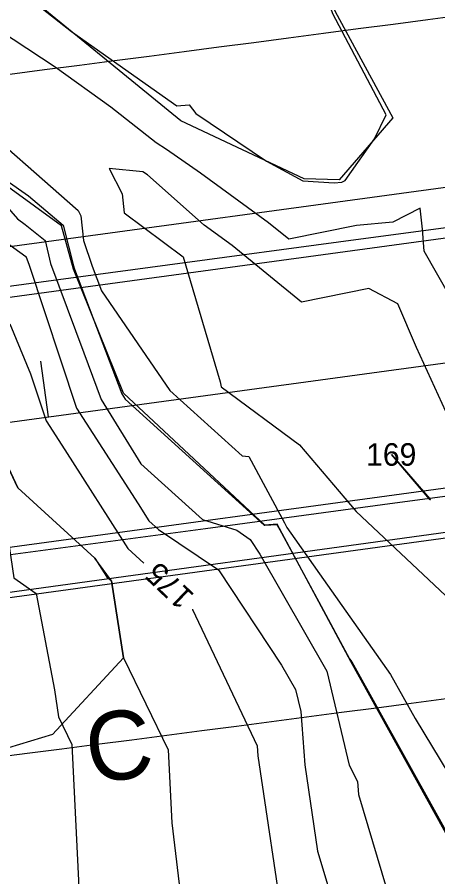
# Model space of a CAD drawing. Extents: x 2086416 to 2115205, y 575507 to 632762.
# Drawn here: x 2111519.4 to 2111556.7, y 581610 to 581686.3 of the extents above; entities that cross this region are included whole.
import ezdxf

# ---------------------------------------------------------------- set-up
doc = ezdxf.new("R2010")
doc.units = 0
for name, color, linetype in [('Default', 7, 'Continuous'), ('DTM Contours Major', 7, 'Continuous'), ('DTM Contours Major Text', 7, 'Continuous'), ('DTM Contours Minor', 7, 'Continuous'), ('DTM Contours Minor Text', 7, 'Continuous'), ('Exist Hydro Stream or Body of Water', 7, 'Continuous'), ('Exist Right of Way Line', 7, 'Continuous'), ('Exist Structure Major Deck Tunnel Box Culvert', 7, 'Continuous'), ('Prop Horizontal Alignment', 7, 'Continuous'), ('Prop Horizontal Alignment Tick Small', 7, 'Continuous'), ('Prop Roadway Bridge', 7, 'Continuous'), ('Prop SS Cut Line', 7, 'Continuous'), ('Prop SS Cut Text', 7, 'Continuous')]:
    doc.layers.add(name, color=color, linetype=linetype)

msp = doc.modelspace()

# ---------------------------------------------------------------- linework, layer by layer
at = {"layer": 'Default'}
for p, q in [((2111430.061, 581649.328), (2112312.029, 581769.688)), ((2111433.036, 581627.53), (2112315.004, 581747.89)), ((2111508.232, 581633.802), (2112048.04, 581707.887))]:
    msp.add_line(p, q, dxfattribs=at)
at = {"layer": 'DTM Contours Major'}
for points in [[(2111563.624, 581644.535), (2111557.765, 581650.557), (2111554.83, 581656.943), (2111553.167, 581660.831), (2111550.584, 581662.207), (2111544.629, 581660.993), (2111538.463, 581666.005), (2111535.965, 581667.83), (2111530.949, 581672.288), (2111530.521, 581672.558), (2111527.53, 581672.834), (2111528.703, 581670.603), (2111528.883, 581668.916), (2111534.119, 581665.006), (2111537.381, 581653.906), (2111537.496, 581653.447), (2111544.432, 581648.303), (2111549.461, 581642.401), (2111557.401, 581634.942)], [(2111518.722, 581659.055), (2111520.566, 581654.612), (2111521.942, 581650.454), (2111523.608, 581647.867), (2111529.184, 581639.091), (2111530.614, 581637.815)], [(2111534.94, 581633.703), (2111534.951, 581633.685), (2111540.685, 581621.595), (2111540.754, 581620.704), (2111543.066, 581605.016), (2111543.152, 581604.727), (2111546.206, 581598.924), (2111547.253, 581597.529), (2111560.711, 581573.535), (2111564.818, 581569.801), (2111569.327, 581557.684), (2111570.482, 581553.108), (2111574.03, 581543.189)]]:
    msp.add_lwpolyline(points, dxfattribs=at)
at = {"layer": 'DTM Contours Minor'}
for points in [[(2111548.202, 581671.635), (2111548.494, 581671.785), (2111551.099, 581675.474), (2111552.125, 581677.605), (2111547.402, 581686.585), (2111547.314, 581686.835), (2111540.681, 581699.19), (2111538.366, 581697.96), (2111532.615, 581704.586), (2111527.172, 581711.478), (2111524.025, 581707.751), (2111520.624, 581705.975), (2111519.423, 581705.653), (2111518.28, 581706.433), (2111512.749, 581713.857), (2111506.226, 581719.408), (2111495.054, 581731.52), (2111493.494, 581731.308)], [(2111487.549, 581730.496), (2111484.48, 581730.078), (2111485.47, 581727.76), (2111493.951, 581708.988), (2111496.972, 581706.844), (2111514.48, 581692.545), (2111515.668, 581691.692), (2111524.198, 581685.007), (2111533.537, 581678.421), (2111534.653, 581678.496), (2111535.245, 581677.738), (2111541.518, 581673.497), (2111544.744, 581671.757), (2111547.518, 581671.576), (2111548.202, 581671.635)], [(2111486.148, 581695.197), (2111501.555, 581683.631), (2111502.551, 581682.906), (2111502.693, 581682.796), (2111520.383, 581670.408), (2111523.452, 581667.816), (2111524.362, 581664.197), (2111524.453, 581663.922), (2111526.096, 581659.621), (2111528.651, 581652.847), (2111528.944, 581652.371), (2111541.304, 581641.187), (2111541.341, 581641.176), (2111541.352, 581641.177), (2111542.435, 581641.236), (2111542.834, 581640.502), (2111546.363, 581633.993), (2111548.886, 581629.315), (2111549.076, 581629.046), (2111561.223, 581607.233)], [(2111480.077, 581692.793), (2111499.229, 581681.074), (2111504.206, 581679.645), (2111504.81, 581680.373), (2111516.403, 581671.803), (2111518.792, 581669.045), (2111519.393, 581668.38), (2111520.086, 581667.875), (2111521.845, 581666.467), (2111522.333, 581664.419), (2111525.28, 581656.47), (2111526.841, 581652.331), (2111530.35, 581646.62), (2111535.812, 581641.677), (2111538.872, 581640.719), (2111540.061, 581639.915), (2111540.925, 581638.611), (2111546.88, 581628.212), (2111548.864, 581619.855), (2111549.576, 581618.418), (2111549.677, 581617.246), (2111553.4, 581604.739), (2111553.764, 581604.049), (2111566.508, 581587.068)], [(2111557.832, 581661.464), (2111555.517, 581665.512), (2111555.366, 581667.475), (2111555.158, 581669.318), (2111552.728, 581668.071), (2111549.514, 581667.794), (2111543.479, 581666.564), (2111541.674, 581668.031), (2111535.656, 581672.428), (2111532.643, 581674.521), (2111531.716, 581675.137), (2111527.674, 581678.306), (2111522.747, 581681.842), (2111516.457, 581685.95), (2111508.951, 581687.161), (2111510.218, 581682.003)], [(2111514.671, 581678.008), (2111524.783, 581669.107), (2111525.034, 581668.631), (2111525.265, 581666.455), (2111526.022, 581664.168), (2111526.859, 581661.975), (2111532.924, 581653.146), (2111539.358, 581647.32), (2111539.946, 581647.287), (2111543.107, 581641.379), (2111543.325, 581640.975), (2111552.535, 581627.92), (2111554.709, 581624.016), (2111564.464, 581607.913)], [(2111497.534, 581672.648), (2111500.186, 581672.634), (2111501.592, 581672.759), (2111508.221, 581674.6), (2111508.4, 581674.547), (2111508.405, 581674.476), (2111508.575, 581674.633), (2111509.925, 581673.393), (2111511.505, 581671.153), (2111513.65, 581668.07), (2111514.341, 581666.679), (2111514.683, 581665.958), (2111514.753, 581665.969), (2111515.61, 581660.191), (2111516.793, 581652.361), (2111517.506, 581647.539), (2111518.546, 581640.1), (2111519.06, 581636.514), (2111521.067, 581635.109), (2111522.669, 581626.555), (2111523.048, 581624.166), (2111524.233, 581621.711), (2111524.91, 581607.809)], [(2111518.215, 581666.433), (2111520.131, 581665.036), (2111520.169, 581665.006), (2111520.179, 581664.962), (2111520.404, 581664.357), (2111524.641, 581651.557), (2111530.11, 581643.065), (2111531.071, 581641.554), (2111531.919, 581640.797), (2111537.24, 581637.201), (2111542.85, 581628.732), (2111544.087, 581626.573), (2111544.545, 581624.642), (2111544.913, 581619.908), (2111546.045, 581612.228), (2111548.276, 581604.733)], [(2111517.321, 581648.942), (2111519.439, 581644.481), (2111526.269, 581638.248), (2111527.298, 581636.629), (2111527.742, 581636.232), (2111528.825, 581629.405), (2111532.774, 581621.227), (2111533.089, 581614.752), (2111534.221, 581605.332)], [(2111552.615, 581647.454), (2111556.02, 581643.513), (2111556.038, 581643.472), (2111556.05, 581643.46), (2111556.069, 581643.416), (2111556.042, 581643.437), (2111556.022, 581643.456), (2111552.615, 581647.454)]]:
    msp.add_lwpolyline(points, dxfattribs=at)
at = {"layer": 'Exist Hydro Stream or Body of Water'}
for points in [[(2111557.095, 581714.198), (2111551.353, 581722.025), (2111533.92, 581727.695), (2111525.554, 581727.773), (2111514.019, 581725.289), (2111507.22, 581720.091), (2111517.385, 581713.698), (2111519.528, 581705.926), (2111524.722, 581706.159), (2111528.702, 581714.798), (2111541.061, 581702.903), (2111547.599, 581686.803), (2111552.73, 581677.358), (2111547.949, 581671.835), (2111544.848, 581671.929), (2111533.907, 581677.08), (2111514.732, 581692.736), (2111494.527, 581709.365), (2111484.151, 581730.439), (2111478.633, 581743.802)], [(2111591.587, 581574.691), (2111583.513, 581582.318), (2111586.645, 581587.276), (2111586.904, 581588.764), (2111586.51, 581589.985), (2111561.568, 581606.344), (2111549.003, 581629.07), (2111542.467, 581641.26), (2111541.348, 581641.183), (2111528.816, 581652.894), (2111524.362, 581663.908), (2111523.315, 581667.748), (2111502.682, 581682.779), (2111481.94, 581698.457), (2111468.579, 581724.282), (2111462.999, 581737.482)]]:
    msp.add_lwpolyline(points, dxfattribs=at)
at = {"layer": 'Exist Right of Way Line'}
msp.add_lwpolyline([(2111379.525, 581602.659), (2111520.243, 581620.919)], dxfattribs=at)
for radius in [24756.937, 24816.937]:
    msp.add_arc((2108326.546, 606231.499), radius, 277.3939111, 277.8562149, dxfattribs=at)
at = {"layer": 'Exist Structure Major Deck Tunnel Box Culvert'}
msp.add_lwpolyline([(2111518.338, 581638.473), (2111518.005, 581640.729), (2111516.542, 581650.631), (2111515.092, 581660.442), (2111514.879, 581661.883), (2111532.718, 581664.281), (2111549.455, 581666.531), (2111567.238, 581668.922), (2111567.482, 581667.278), (2111568.946, 581657.382), (2111570.384, 581647.665), (2111570.703, 581645.511), (2111552.911, 581643.12), (2111536.107, 581640.862), (2111518.338, 581638.473)], dxfattribs=at)
at = {"layer": 'Prop Horizontal Alignment'}
msp.add_line((2111431.548, 581638.429), (2112404.465, 581771.2), dxfattribs=at)
at = {"layer": 'Prop Horizontal Alignment Tick Small'}
msp.add_line((2111522.151, 581650.793), (2111521.475, 581655.747), dxfattribs=at)
at = {"layer": 'Prop Roadway Bridge'}
for p, q in [((2111585.034, 581674.934), (2111495.86, 581662.765)), ((2111508.215, 581633.332), (2111597.389, 581645.501))]:
    msp.add_line(p, q, dxfattribs=at)
at = {"layer": 'Prop SS Cut Line'}
for p, q in [((2111519.439, 581644.481), (2111517.321, 581648.942)), ((2111526.269, 581638.248), (2111519.439, 581644.481)), ((2111527.742, 581636.232), (2111526.269, 581638.248)), ((2111528.825, 581629.405), (2111527.742, 581636.232)), ((2111528.825, 581629.405), (2111522.497, 581622.577)), ((2111522.497, 581622.577), (2111513.072, 581619.756))]:
    msp.add_line(p, q, dxfattribs=at)

# ---------------------------------------------------------------- texts
at = {"layer": 'DTM Contours Major Text'}
msp.add_text('175', height=2, rotation=136.44274, dxfattribs=at).set_placement((2111535.191, 581634.975))
at = {"layer": 'DTM Contours Minor Text'}
msp.add_text('169', height=2, dxfattribs=at).set_placement((2111550.355, 581646.454))
at = {"layer": 'Prop SS Cut Text'}
msp.add_text('C', height=6.104, rotation=7.77101, dxfattribs=at).set_placement((2111525.877, 581618.198))

doc.saveas('drawing.dxf')
